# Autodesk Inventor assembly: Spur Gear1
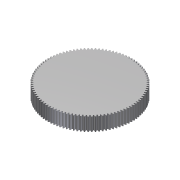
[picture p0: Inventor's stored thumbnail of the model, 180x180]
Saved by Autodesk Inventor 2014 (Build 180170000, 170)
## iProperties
Created: 2011-01
Part Number: Spur Gear1
Document SubType Name: Assembly
Designer: Beta-8540w
Categories: <?xml version="1.0" encoding="UTF-16"?> <MemberInstance><Categories><FamilyTemplate/><ParamToTemplateMap><ParamToTemplate><ParamToTemplate CategoryParameter="//
ClientObjectVersion: 1
Author: Beta-8540w
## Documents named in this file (2)
- C:\Inventor 2014 Essentials\Assemblies\Chapter 09\Design Accelerators\Spur Gear c09-02.iam
- C:\Inventor 2014 Essentials\Assemblies\Chapter 09\Design Accelerators\Spur Gear c09-02.ipt
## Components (1 placed, 1 different names)
1. Spur Gear2:1
